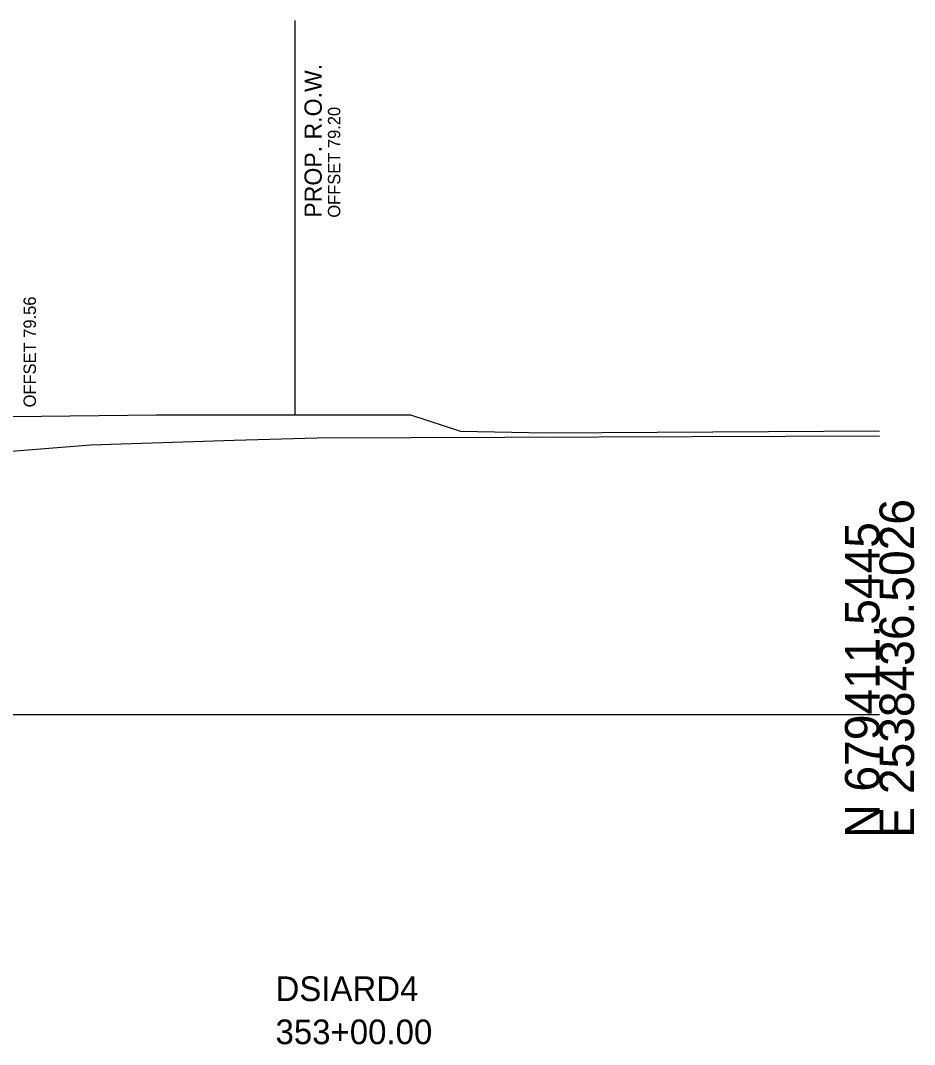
# Model space of a CAD drawing. Extents: x -26 to 1603, y -30 to 14537.
# Drawn here: x 230.3 to 302.8, y 3973.2 to 4056.3 of the extents above; entities that cross this region are included whole.
import ezdxf

# ---------------------------------------------------------------- set-up
doc = ezdxf.new("R2010")
doc.units = 0
for name, color, linetype in [('DESIGN - ROW - Right-of-Way and Easement Labels', 7, 'Continuous'), ('DESIGN - ROW - Right-of-Way Linework', 7, 'Continuous'), ('DESIGN - SHEET - Light Grid', 7, 'Continuous'), ('DESIGN - TYPICAL - Slope Tie Text', 7, 'Continuous'), ('DESIGN - TYPICAL - Warning Text', 7, 'Continuous'), ('SURVEY - GROUND - Top of Ground', 7, 'Continuous')]:
    doc.layers.add(name, color=color, linetype=linetype)

msp = doc.modelspace()

# ---------------------------------------------------------------- linework, layer by layer
at = {"layer": 'DESIGN - ROW - Right-of-Way Linework'}
msp.add_line((252.6, 4024.307), (252.6, 4056.307), dxfattribs=at)
at = {"layer": 'DESIGN - SHEET - Light Grid'}
msp.add_line((150, 4000), (300, 4000), dxfattribs=at)
at = {"layer": 'SURVEY - GROUND - Top of Ground'}
for points in [[(93.134, 4021.857), (113.558, 4022.685), (114.501, 4022.739), (115.797, 4022.763), (133.149, 4023.026), (146.9, 4023.671), (150, 4023.759), (159.855, 4024.041), (168.486, 4024.048), (179.062, 4023.706), (188.724, 4023.8), (198.709, 4023.902), (209.157, 4024.012), (219.269, 4024.064), (229.676, 4024.168), (241.337, 4024.316), (255.324, 4024.305), (261.958, 4024.306), (266.001, 4022.98), (272.969, 4022.849), (300, 4023.014)], [(0, 4000.906), (7.395, 4001.323), (20.588, 4002.367), (28.067, 4002.737), (55.769, 4004.72), (99.054, 4007.087), (131.89, 4011.94), (144.909, 4012.196), (150, 4012.171), (179.548, 4012.023), (180.331, 4012.075), (185.366, 4013.565), (205.192, 4019.194), (207.632, 4019.595), (235.992, 4021.867), (247.656, 4022.252), (254.365, 4022.453), (300, 4022.604)]]:
    msp.add_lwpolyline(points, dxfattribs=at)

# ---------------------------------------------------------------- texts
at = {"layer": 'DESIGN - ROW - Right-of-Way and Easement Labels'}
for s, height, p in [('PROP. R.O.W.', 1.4, (254.75, 4040.307)), ('OFFSET 79.20', 1, (256.25, 4040.307))]:
    msp.add_text(s, height=height, rotation=90, dxfattribs=at).set_placement(p)
at = {"layer": 'DESIGN - SHEET - Light Grid'}
for s, p in [('E 2538436.5026', (302.8, 3990)), ('N 679411.5445', (300, 3990))]:
    msp.add_text(s, height=2.8, rotation=90, dxfattribs=at).set_placement(p)
at = {"layer": 'DESIGN - TYPICAL - Slope Tie Text'}
msp.add_text('OFFSET 79.56', height=1, rotation=90, dxfattribs=at).set_placement((231.558, 4024.917))
at = {"layer": 'DESIGN - TYPICAL - Warning Text'}
for s, p in [('DSIARD4', (251, 3976.75)), ('353+00.00', (251, 3973.25))]:
    msp.add_text(s, height=2, dxfattribs=at).set_placement(p)

doc.saveas('drawing.dxf')
